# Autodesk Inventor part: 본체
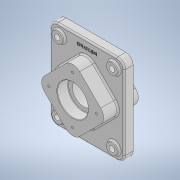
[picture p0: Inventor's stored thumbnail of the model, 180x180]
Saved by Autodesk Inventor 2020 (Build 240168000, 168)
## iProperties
Created: 2021-07
Part Number: 본체
Material: 일반
Document SubType Name: Modeling
Designer: Owner
Density: 1 g/cm^3
Appearance: 기본값
Mass: 808.432 g
Surface Area: 958.051 cm^2
Volume: 808.432 cm^3
Author: Owner
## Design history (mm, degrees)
sketch "스케치1"
  geometry: L1 (-75, 90)-(75, 90); L2 (75, 90)-(75, -90); L3 (75, -90)-(-75, -90); L4 (-75, -90)-(-75, 90); L5 (-75, 90)-(75, -90); L6 (75, 90)-(-75, -90); 1 further point
  constraints: 12 end point, 2 midpoint, 2 parallel, 1 horizontal, 1 perpendicular
  dimensions: "d0" = 150 distance of L1.start L1.end; "d1" = 180 distance of L1.end L2.end
extrude "돌출1" new body sketch "스케치1" stored distance "d2" = 18; taper "d3" = 0 deg
fillet "모깎기1" dims "d4" = 15
fillet "모깎기2" dims "d5" = 3
sketch "스케치2"
  geometry: L1 (-55, 90)-(55, 90); L2 (60, 90)-(-60, 90) reference; L3 (55, -70)-(55, 70); C1 r 11 at (55, 70); 3 further points
  constraints: 4 end point, 3 midpoint, 1 centre point, 1 coincident, 1 horizontal, 1 horizontal alignment, 1 vertical
  dimensions: "d6" = 110 distance of L1.start L1.end; "d7" = 140 distance of L3.start L3.end; "d8" = 22 diameter of C1
extrude "돌출2" join sketch "스케치2" distance "d9" = 5; taper "d10" = 0 deg
sketch "스케치3"
  geometry: C1 r 11 at (0, 0) reference; 2 further points
  constraints: 1 coincident
hole "구멍1" sketch "스케치3" at (0, 0) diameter "d11" = 11; stored, may be unused: countersink angle "d15" = 90 deg, drill point angle "d17" = 118 deg; dims "d12" = 8, "d13" = 4, "d14" = 2, "d16" = 11
sketch "스케치5"
  geometry: L1 (0, 70.711)-(-70.711, 0); L2 (-70.711, 0)-(0, -70.711); L3 (0, -70.711)-(70.711, 0); L4 (70.711, 0)-(0, 70.711); 1 further point
  constraints: 8 end point, 2 horizontal alignment, 2 parallel, 2 vertical alignment, 1 perpendicular
  dimensions: "d19" = 100 distance between parallel lines of L3 L1
extrude "돌출3" join sketch "스케치5" distance "d20" = 29; taper "d21" = 0 deg
sketch "스케치6"
  geometry: L1 (0, 70.711)-(-70.711, 0) reference; L2 (-70.711, 0)-(0, -70.711) reference; L3 (0, 70.711)-(-70.711, 0); L4 (-70.711, 0)-(0, -70.711); L5 (0, -70.711)-(70.711, 0); L6 (70.711, 0)-(0, 70.711); 2 further points
  constraints: 8 end point, 2 parallel, 2 perpendicular
extrude "돌출4" join sketch "스케치6" distance "d22" = 23; taper "d23" = 0 deg
fillet "모깎기3" dims "d24" = 20
sketch "스케치7" dims "d25" = 96
  geometry: L1 (0, 0)-(0, 48); 1 further point
  constraints: 2 end point, 1 coincident, 1 vertical, 1 vertical alignment, 2 other
hole "구멍2" sketch "스케치7" at (0, 48) diameter "d26" = 4.917; stored, may be unused: countersink angle "d30" = 90 deg, drill point angle "d32" = 118 deg; dims "d27" = 10, "d28" = 4, "d29" = 2, "d31" = 13
node "작업 평면2"
sketch "스케치8"
  geometry: L1 (56.569, 38)-(14.142, 38) reference; L2 (31, 38)-(31, 16); L3 (31, 16)-(22.5, 16); L4 (22.5, 16)-(22.5, -10); L5 (22.5, -10)-(31, -10); L6 (31, -10)-(31, -32); L7 (14.142, -32)-(56.569, -32) reference; L8 (-14.142, 38)-(14.142, 38) reference; L9 (0, 38)-(0, -32); L10 (14.142, -32)-(-14.142, -32) reference; 1 further point
  constraints: 12 end point, 4 perpendicular, 4 point on line, 2 midpoint
  dimensions: "d35" = 62 diameter of L2 L9; "d36" = 45 diameter of L4 L9; "d37" = 22 distance of L2.start L2.end; "d38" = 22 distance of L5.end L6.end
revolve "회전1" sketch "스케치8" stored, may be unused: angle "d39" = 90 deg
fillet "모깎기4" dims "d40" = 1
chamfer "모따기1" distance "d41" = 1; stored, may be unused: second distance "d42" = 2, angle "d43" = 45 deg
chamfer "모따기2" distance "d44" = 1; stored, may be unused: second distance "d45" = 2, angle "d46" = 45 deg
fillet "모깎기5" dims "d47" = 3
sketch "스케치9"
  geometry: L1 (-75, -75)-(-75, 75) reference; L2 (60, 90)-(-60, 90) reference; A1 r 20 centre (0, 42.426) between (14.142, 56.569) and (-14.142, 56.569) reference; 3 further points
  constraints: 1 horizontal alignment, 1 point on circle, 1 vertical alignment, 1 other
  dimensions: "d70" = 15 distance from line of point (0, 75) L2 (derived)
feature "엠보싱1" sketch "스케치9" dims "d0" = 150, "d1" = 180, "d55" = 0.5, "d56" = 0
fillet "모깎기6" dims "d57" = 3
fillet "모깎기7" dims "d58" = 3
sketch "스케치10"
  geometry: L1 (0, 0)-(0, 48); C1 r 48 at (0, 0); C2 r 22.5 at (0, 0) reference; C3 r 2.458 at (0, 48) reference; 1 further point
  constraints: 2 end point, 1 centre point, 1 coincident, 1 vertical
  dimensions: "d59" = 96 diameter of C1
hole "구멍3" sketch "스케치10" at (0, 48) diameter "d60" = 4.917; stored, may be unused: countersink angle "d64" = 90 deg, drill point angle "d66" = 118 deg; dims "d61" = 10, "d62" = 4, "d63" = 2, "d65" = 13
node "솔리드1"
mirror "미러1"
mirror "미러2"
mirror "미러3"
mirror "미러4"
pattern_circular "원형 패턴1" dims angle "d49" = 360 deg
pattern_circular "원형 패턴3" dims angle "d68" = 360 deg
node "작업 평면1"
feature "A9D066F2-1C7D-4E18-AEED-F7BC21143FA4" dims "d11" = 11, "d12" = 8, "d13" = 4, "d14" = 2, "d15" = 90 deg, "d16" = 11, "d17" = 118 deg
other parameters: "d33" = 0
